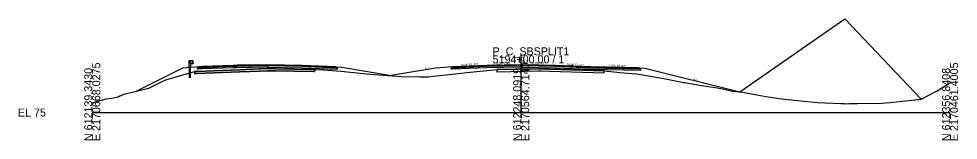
# Model space of a CAD drawing. Extents: x -26 to 1303, y -3010 to 12033.
# Drawn here: x -25.7 to 302.8, y 11490.3 to 11532.8 of the extents above; entities that cross this region are included whole.
import ezdxf

# ---------------------------------------------------------------- set-up
doc = ezdxf.new("R2010")
doc.units = 0
for name, color, linetype in [('RD_GPK_XS_Cell', 7, 'Continuous'), ('RD_PD_Final_TrvlWay', 7, 'Continuous'), ('RD_Sketch10', 7, 'Continuous'), ('RD_XS_Base', 7, 'Continuous'), ('RD_XS_ExGround', 7, 'Continuous'), ('RD_XS_ExPaveRet', 7, 'Continuous'), ('RD_XS_GR', 7, 'Continuous'), ('RD_XS_Greenside', 7, 'Continuous'), ('RD_XS_Pave', 7, 'Continuous'), ('RD_XS_PaveOvlay_CP', 7, 'Continuous'), ('RD_XS_TieSlope', 7, 'Continuous'), ('RD_XS_TX_Elev_EX', 7, 'Continuous'), ('RD_XS_TX_Elev_PR', 7, 'Continuous'), ('RD_XS_TX_Slope', 7, 'Continuous')]:
    doc.layers.add(name, color=color, linetype=linetype)

msp = doc.modelspace()

# ---------------------------------------------------------------- linework, layer by layer
at = {"layer": 'RD_GPK_XS_Cell'}
for p, q in [((150, 11500), (150, 11520)), ((0, 11500), (150, 11500)), ((150, 11500), (300, 11500))]:
    msp.add_line(p, q, dxfattribs=at)
at = {"layer": 'RD_PD_Final_TrvlWay'}
msp.add_lwpolyline([(34.41, 11512.16), (34.41, 11515.76), (33.91, 11515.72), (33.91, 11512.16)], dxfattribs=at)
at = {"layer": 'RD_Sketch10'}
msp.add_lwpolyline([(226.46, 11507.2), (263.23, 11532.78), (289.88, 11504.66)], dxfattribs=at)
at = {"layer": 'RD_XS_Base'}
for p, q in [((36.75, 11515.2), (36.75, 11515.65)), ((36.75, 11515.65), (36.8, 11515.65)), ((36.75, 11515.15), (36.75, 11515.2)), ((36.8, 11515.15), (36.75, 11515.15)), ((36.8, 11515.65), (37.25, 11515.67)), ((37.25, 11515.17), (36.8, 11515.15)), ((37.25, 11515.67), (38.51, 11515.72)), ((38.51, 11515.22), (37.25, 11515.17)), ((38.51, 11515.72), (49.25, 11516.15)), ((49.25, 11515.65), (38.51, 11515.22)), ((49.25, 11516.15), (50.68, 11516.18)), ((50.68, 11515.68), (49.25, 11515.65)), ((50.68, 11516.18), (61.25, 11516.39)), ((61.25, 11515.89), (50.68, 11515.68)), ((61.25, 11516.41), (61.25, 11516.55)), ((61.25, 11516.55), (61.25, 11515.98)), ((61.25, 11516.39), (61.25, 11516.55)), ((61.25, 11516.55), (61.25, 11515.89)), ((61.25, 11516.39), (61.25, 11516.41)), ((61.25, 11516.39), (61.25, 11515.95)), ((61.25, 11516.39), (61.25, 11515.89)), ((73.25, 11516.15), (61.25, 11516.39)), ((61.25, 11516.39), (61.25, 11516.39)), ((61.25, 11515.98), (61.25, 11515.89)), ((61.25, 11515.95), (61.25, 11515.89)), ((61.25, 11515.89), (61.25, 11515.89)), ((61.25, 11515.89), (61.25, 11515.89)), ((61.25, 11515.89), (73.25, 11515.65)), ((85.25, 11515.67), (73.25, 11516.15)), ((73.25, 11515.65), (85.75, 11515.15)), ((75.25, 11516.07), (75.25, 11516.07)), ((75.25, 11515.57), (75.25, 11515.57)), ((85.75, 11515.65), (85.25, 11515.67)), ((85.25, 11515.67), (85.25, 11515.67)), ((85.75, 11515.15), (85.75, 11515.65)), ((85.75, 11515.65), (85.75, 11515.65)), ((85.75, 11515.15), (85.75, 11515.15)), ((85.75, 11515.15), (85.75, 11515.15)), ((125.5, 11515.66), (126, 11515.68)), ((125.5, 11515.16), (125.5, 11515.66)), ((125.5, 11515.66), (125.5, 11515.66)), ((126, 11515.18), (125.5, 11515.16)), ((125.5, 11515.16), (125.5, 11515.16)), ((125.5, 11515.16), (125.5, 11515.16)), ((126, 11515.68), (138, 11516.16)), ((126, 11515.68), (126, 11515.68)), ((138, 11515.66), (126, 11515.18)), ((126, 11515.18), (126, 11515.18)), ((136, 11516.08), (136, 11516.08)), ((136, 11515.58), (136, 11515.58)), ((138, 11516.16), (150, 11516.4)), ((150, 11515.9), (138, 11515.66)), ((150, 11516.4), (150, 11516.55)), ((150, 11516.55), (150, 11515.9)), ((150, 11516.4), (150, 11516.4)), ((162, 11516.16), (150, 11516.4)), ((150, 11516.4), (150, 11516.4)), ((150, 11516.4), (150, 11515.9)), ((150, 11515.9), (150, 11515.9)), ((150, 11515.9), (162, 11515.66)), ((150, 11515.9), (150, 11515.9)), ((174, 11515.68), (162, 11516.16)), ((162, 11516.16), (162, 11516.16)), ((162, 11515.66), (162, 11515.66)), ((162, 11515.66), (174, 11515.18)), ((191.3, 11515.33), (174, 11515.68)), ((174, 11515.68), (174, 11515.68)), ((174, 11515.18), (174, 11515.18)), ((174, 11515.18), (191.8, 11514.82)), ((191.8, 11515.32), (191.3, 11515.33)), ((191.3, 11515.33), (191.3, 11515.33)), ((191.8, 11514.82), (191.8, 11515.32)), ((191.8, 11515.32), (191.8, 11515.32)), ((191.8, 11514.82), (191.8, 11514.82)), ((191.8, 11514.82), (191.8, 11514.82))]:
    msp.add_line(p, q, dxfattribs=at)
at = {"layer": 'RD_XS_ExGround'}
msp.add_lwpolyline([(0, 11503.16), (0.85, 11503.63), (1.09, 11503.73), (4.87, 11504.76), (6.79, 11504.98), (9.04, 11505.51), (9.7, 11505.78), (11.46, 11506.53), (12.86, 11506.84), (19.84, 11508.5), (21.24, 11509.22), (24.72, 11510.91), (25.74, 11511.39), (32.1, 11513.26), (35.86, 11514.32), (48.24, 11514.83), (61.42, 11515.36), (77.35, 11515.09), (77.7, 11515.09), (77.84, 11515.08), (78.16, 11515.06), (80.83, 11514.88), (86.96, 11514.5), (94.89, 11513.61), (95.82, 11513.5), (98.76, 11513.29), (108.05, 11512.55), (114.6, 11512.52), (117.63, 11512.53), (119.19, 11512.68), (127.08, 11513.5), (131.01, 11513.94), (141.5, 11515.02), (156.22, 11515.29), (156.97, 11515.3), (159.88, 11515.2), (179.08, 11514.58), (184.51, 11514.05), (190.33, 11513.5), (192.49, 11513.12), (199.9, 11511.84), (202.19, 11511.47), (205.73, 11510.69), (206.61, 11510.5), (206.86, 11510.46), (207.07, 11510.44), (213.11, 11509.48), (218.7, 11508.6), (219.16, 11508.5), (219.84, 11508.39), (223.94, 11507.51), (227.41, 11507.08), (233.73, 11505.99), (236.35, 11505.5), (240.18, 11504.95), (243.38, 11504.5), (248.92, 11503.96), (253.68, 11503.51), (261.75, 11503.15), (262.92, 11503.1), (263.49, 11503.07), (264.57, 11503.12), (267.55, 11503.19), (276.25, 11503.21), (278.92, 11503.51), (283.33, 11503.95), (289.88, 11504.66), (295.23, 11507.47), (300, 11510.41)], dxfattribs=at)
at = {"layer": 'RD_XS_ExPaveRet'}
for points in [[(77.68, 11515.09), (77.7, 11515.09), (77.7, 11515), (77.7, 11514.34), (77.68, 11514.34), (77.33, 11514.34), (64.22, 11514.56), (61.42, 11514.61), (58.53, 11514.49), (51.6, 11514.21), (36.4, 11513.6), (35.86, 11513.57), (35.86, 11514.02), (35.86, 11514.32), (36.4, 11514.35), (51.6, 11514.96), (58.53, 11515.24), (61.42, 11515.36), (64.22, 11515.31), (77.33, 11515.09), (77.68, 11515.09)], [(77.33, 11515.09), (64.22, 11515.31), (61.42, 11515.36), (58.53, 11515.24), (51.6, 11514.96), (36.4, 11514.35), (35.86, 11514.32), (35.86, 11514.02), (35.86, 11513.57), (36.4, 11513.6), (51.6, 11514.21), (58.53, 11514.49), (61.42, 11514.61), (64.22, 11514.56), (77.33, 11514.34), (77.68, 11514.34), (77.7, 11514.34), (77.7, 11515), (77.7, 11515.09), (77.68, 11515.09), (77.33, 11515.09)], [(159.88, 11515.2), (156.97, 11515.3), (156.97, 11515.3), (156.22, 11515.29), (156.22, 11515.29), (141.5, 11515.02), (141.5, 11515.02), (141.5, 11515.02), (141.5, 11514.27), (141.5, 11514.27), (156.22, 11514.54), (156.22, 11514.54), (156.97, 11514.55), (156.97, 11514.55), (159.88, 11514.45), (159.88, 11514.45), (179.08, 11513.83), (179.08, 11514.58), (179.08, 11514.58), (159.88, 11515.2), (159.88, 11515.2)], [(159.88, 11515.2), (156.97, 11515.3), (156.22, 11515.29), (141.5, 11515.02), (141.5, 11514.27), (156.22, 11514.54), (156.97, 11514.55), (159.88, 11514.45), (179.08, 11513.83), (179.08, 11514.58), (159.88, 11515.2)]]:
    msp.add_lwpolyline(points, dxfattribs=at)
at = {"layer": 'RD_XS_GR'}
for p, q in [((33.91, 11515.72), (33.91, 11518.16)), ((33.91, 11518.16), (34.16, 11518.16)), ((34.41, 11515.76), (33.91, 11515.72)), ((34.16, 11518.16), (34.41, 11518.16)), ((34.41, 11518.16), (34.41, 11515.76)), ((34.41, 11516.99), (34.41, 11518.16)), ((34.41, 11518.16), (35.08, 11518.16)), ((35.08, 11516.99), (34.41, 11516.99)), ((35.08, 11518.16), (35.08, 11516.99)), ((35.32, 11517.89), (35.08, 11518.16)), ((35.08, 11518.16), (35.08, 11517.11)), ((35.08, 11517.57), (35.1, 11517.6)), ((35.32, 11517.31), (35.08, 11517.57)), ((35.08, 11517.11), (35.08, 11516.99)), ((35.08, 11516.99), (35.1, 11517.02)), ((35.1, 11517.6), (35.35, 11517.86)), ((35.1, 11517.02), (35.35, 11517.28)), ((35.35, 11517.86), (35.32, 11517.89)), ((35.35, 11517.28), (35.32, 11517.31))]:
    msp.add_line(p, q, dxfattribs=at)
at = {"layer": 'RD_XS_Greenside'}
for p, q in [((31.6, 11515.54), (15.43, 11507.45)), ((87.25, 11515.83), (104.57, 11512.94)), ((120, 11515.51), (104.57, 11512.94)), ((193.3, 11515.49), (226.46, 11507.2))]:
    msp.add_line(p, q, dxfattribs=at)
at = {"layer": 'RD_XS_Pave'}
for p, q in [((38.51, 11516.04), (37.25, 11515.99)), ((37.25, 11515.99), (37.25, 11515.85)), ((38.51, 11515.88), (37.25, 11515.83)), ((37.25, 11515.83), (38.51, 11515.88)), ((37.25, 11515.85), (37.25, 11515.83)), ((37.25, 11515.83), (37.25, 11515.69)), ((37.25, 11515.67), (38.51, 11515.72)), ((37.25, 11515.69), (37.25, 11515.67)), ((49.25, 11516.47), (38.51, 11516.04)), ((49.25, 11516.31), (38.51, 11515.88)), ((38.51, 11515.88), (49.25, 11516.31)), ((38.51, 11515.72), (49.25, 11516.15)), ((50.68, 11516.5), (49.25, 11516.47)), ((50.68, 11516.34), (49.25, 11516.31)), ((49.25, 11516.31), (50.68, 11516.34)), ((49.25, 11516.15), (50.68, 11516.18)), ((61.25, 11516.71), (50.68, 11516.5)), ((61.25, 11516.55), (50.68, 11516.34)), ((50.68, 11516.34), (61.25, 11516.55)), ((50.68, 11516.18), (61.25, 11516.39)), ((73.25, 11516.47), (61.25, 11516.71)), ((61.25, 11516.41), (61.25, 11516.55)), ((61.25, 11516.55), (61.25, 11516.41)), ((61.25, 11516.39), (61.25, 11516.55)), ((61.25, 11516.55), (73.25, 11516.31)), ((73.25, 11516.31), (61.25, 11516.55)), ((61.25, 11516.55), (61.25, 11516.39)), ((61.25, 11516.39), (61.25, 11516.41)), ((61.25, 11516.41), (61.25, 11516.39)), ((61.25, 11516.39), (61.25, 11516.39)), ((61.25, 11516.39), (61.25, 11516.39)), ((61.25, 11516.39), (73.25, 11516.15)), ((85.25, 11515.99), (73.25, 11516.47)), ((73.25, 11516.31), (85.25, 11515.83)), ((85.25, 11515.83), (73.25, 11516.31)), ((73.25, 11516.15), (85.25, 11515.67)), ((75.25, 11516.39), (75.25, 11516.39)), ((75.25, 11516.23), (75.25, 11516.23)), ((75.25, 11516.23), (75.25, 11516.23)), ((75.25, 11516.07), (75.25, 11516.07)), ((85.25, 11515.83), (85.25, 11515.99)), ((85.25, 11515.99), (85.25, 11515.99)), ((85.25, 11515.83), (85.25, 11515.83)), ((85.25, 11515.83), (85.25, 11515.83)), ((85.25, 11515.67), (85.25, 11515.83)), ((85.25, 11515.83), (85.25, 11515.83)), ((85.25, 11515.67), (85.25, 11515.67)), ((85.25, 11515.67), (85.25, 11515.67)), ((138, 11516.47), (126, 11515.99)), ((138, 11516.31), (126, 11515.83)), ((126, 11515.83), (138, 11516.31)), ((126, 11515.68), (138, 11516.16)), ((126, 11515.99), (126, 11515.99)), ((126, 11515.99), (126, 11515.83)), ((126, 11515.83), (126, 11515.83)), ((126, 11515.83), (126, 11515.68)), ((126, 11515.83), (126, 11515.83)), ((126, 11515.83), (126, 11515.83)), ((126, 11515.68), (126, 11515.68)), ((126, 11515.68), (126, 11515.68)), ((136, 11516.39), (136, 11516.39)), ((136, 11516.23), (136, 11516.23)), ((136, 11516.23), (136, 11516.23)), ((136, 11516.08), (136, 11516.08)), ((150, 11516.71), (138, 11516.47)), ((150, 11516.55), (138, 11516.31)), ((138, 11516.31), (150, 11516.55)), ((138, 11516.16), (150, 11516.4)), ((162, 11516.47), (150, 11516.71)), ((150, 11516.4), (150, 11516.55)), ((150, 11516.55), (162, 11516.31)), ((162, 11516.31), (150, 11516.55)), ((150, 11516.55), (150, 11516.55)), ((150, 11516.55), (150, 11516.4)), ((150, 11516.4), (150, 11516.4)), ((150, 11516.4), (150, 11516.4)), ((150, 11516.4), (150, 11516.4)), ((150, 11516.4), (162, 11516.16)), ((174, 11515.99), (162, 11516.47)), ((162, 11516.47), (162, 11516.47)), ((162, 11516.31), (162, 11516.31)), ((162, 11516.31), (174, 11515.83)), ((174, 11515.83), (162, 11516.31)), ((162, 11516.31), (162, 11516.31)), ((162, 11516.16), (162, 11516.16)), ((162, 11516.16), (174, 11515.68)), ((191.3, 11515.65), (174, 11515.99)), ((174, 11515.99), (174, 11515.99)), ((174, 11515.83), (174, 11515.83)), ((174, 11515.83), (191.3, 11515.49)), ((191.3, 11515.49), (174, 11515.83)), ((174, 11515.83), (174, 11515.83)), ((174, 11515.68), (174, 11515.68)), ((174, 11515.68), (191.3, 11515.33)), ((191.3, 11515.49), (191.3, 11515.65)), ((191.3, 11515.65), (191.3, 11515.65)), ((191.3, 11515.49), (191.3, 11515.49)), ((191.3, 11515.49), (191.3, 11515.49)), ((191.3, 11515.33), (191.3, 11515.49)), ((191.3, 11515.49), (191.3, 11515.49)), ((191.3, 11515.33), (191.3, 11515.33)), ((191.3, 11515.33), (191.3, 11515.33))]:
    msp.add_line(p, q, dxfattribs=at)
at = {"layer": 'RD_XS_PaveOvlay_CP'}
for p, q in [((37.25, 11515.99), (49.25, 11516.47)), ((49.25, 11516.47), (61.25, 11516.71)), ((61.25, 11516.71), (73.25, 11516.47)), ((73.25, 11516.47), (85.25, 11515.99)), ((138, 11516.47), (126, 11515.99)), ((126, 11515.99), (126, 11515.99)), ((136, 11516.39), (136, 11516.39)), ((150, 11516.71), (138, 11516.47)), ((162, 11516.47), (150, 11516.71)), ((174, 11515.99), (162, 11516.47)), ((162, 11516.47), (162, 11516.47)), ((191.3, 11515.65), (174, 11515.99)), ((174, 11515.99), (174, 11515.99)), ((191.3, 11515.65), (191.3, 11515.65))]:
    msp.add_line(p, q, dxfattribs=at)
at = {"layer": 'RD_XS_TieSlope'}
for p, q in [((37.25, 11515.99), (31.6, 11515.54)), ((85.25, 11515.99), (87.25, 11515.83)), ((126, 11515.99), (120, 11515.51)), ((191.3, 11515.65), (193.3, 11515.49))]:
    msp.add_line(p, q, dxfattribs=at)

# ---------------------------------------------------------------- texts
at = {"layer": 'RD_GPK_XS_Cell'}
for s, p in [('P_C_SBSPLIT1', (140, 11520)), ('5194+00.00 / 1', (140, 11517.2)), ('EL 75', (-26, 11498.6))]:
    msp.add_text(s, height=2.8, dxfattribs=at).set_placement(p)
for s, p in [('N 612139.3430', (0, 11490)), ('E 2170668.0275', (2.8, 11490)), ('N 612248.0919', (150, 11490)), ('E 2170564.7140', (152.8, 11490)), ('N 612356.8408', (300, 11490)), ('E 2170461.4005', (302.8, 11490))]:
    msp.add_text(s, height=2.8, rotation=90, dxfattribs=at).set_placement(p)
at = {"layer": 'RD_XS_TX_Elev_EX'}
msp.add_text('90.17', height=0.6, rotation=90, dxfattribs=at).set_placement((149.66, 11517.31))
at = {"layer": 'RD_XS_TX_Elev_PR'}
msp.add_text('91.71', height=1, rotation=90, dxfattribs=at).set_placement((151.17, 11516.84))
at = {"layer": 'RD_XS_TX_Slope'}
for s, rotation, p in [('6:1', 9.4623, (116.41, 11514.97)), ('0.040 FT./FT.', 2.2906, (128.93, 11516.21)), ('0.020 FT./FT.', 1.1458, (140.27, 11516.68)), ('0.020 FT./FT.', 358.8542, (153.94, 11516.73)), ('0.040 FT./FT.', 357.7094, (165.94, 11516.41)), ('0.020 FT./FT.', 358.8542, (180.59, 11515.96)), ('4:1', 345.9638, (210.04, 11511.36))]:
    msp.add_text(s, height=0.75, rotation=rotation, dxfattribs=at).set_placement(p)

doc.saveas('drawing.dxf')
